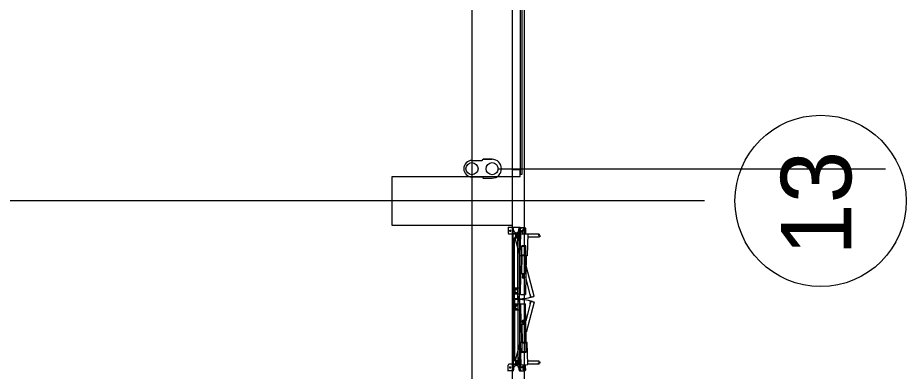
# Model space of a CAD drawing. Extents: x -264031 to -263588, y -1242281 to -1242059.
# Drawn here: x -263801.19 to -263790.15, y -1242163 to -1242158.61 of the extents above; entities that cross this region are included whole.
import ezdxf

# ---------------------------------------------------------------- set-up
doc = ezdxf.new("R2010")
doc.units = 0
doc.layers.add('HESCON_OSI_STAVBY_KFA', color=7, linetype='Continuous')
doc.layers.add('KFA_2D_SITUACIA_DSP', color=7, linetype='Continuous')

msp = doc.modelspace()

# ---------------------------------------------------------------- linework, layer by layer
at = {"layer": 'HESCON_OSI_STAVBY_KFA'}
for p, q in [((-263795.543, -1242083.237), (-263795.543, -1242246.707)), ((-263792.653, -1242160.882), (-263909.343, -1242160.882)), ((-263792.653, -1242160.882), (-263792.653, -1242160.882))]:
    msp.add_line(p, q, dxfattribs=at)
msp.add_circle((-263791.21, -1242160.882), 1.064, dxfattribs=at)
at = {"layer": 'KFA_2D_SITUACIA_DSP'}
for p, q in [((-263795.043, -1242101.769), (-263795.043, -1242226.995)), ((-263794.943, -1242158.452), (-263794.943, -1242160.552)), ((-263794.918, -1242160.552), (-263794.918, -1242158.452)), ((-263795.543, -1242160.379), (-263795.418, -1242160.379)), ((-263795.418, -1242160.379), (-263795.404, -1242160.365)), ((-263795.293, -1242160.365), (-263795.404, -1242160.365)), ((-263795.404, -1242160.365), (-263795.293, -1242160.365)), ((-263795.038, -1242160.582), (-263796.538, -1242160.582)), ((-263796.538, -1242160.582), (-263796.538, -1242161.182)), ((-263795.218, -1242160.485), (-263790.403, -1242160.482)), ((-263794.943, -1242160.497), (-263795.043, -1242160.497)), ((-263795.043, -1242160.497), (-263795.043, -1242160.577)), ((-263795.043, -1242160.577), (-263794.943, -1242160.577)), ((-263795.038, -1242161.182), (-263795.038, -1242160.582)), ((-263794.943, -1242160.537), (-263794.943, -1242160.497)), ((-263794.943, -1242160.577), (-263794.943, -1242160.537)), ((-263794.943, -1242160.552), (-263794.918, -1242160.552)), ((-263795.543, -1242160.585), (-263795.418, -1242160.585)), ((-263795.418, -1242160.585), (-263795.404, -1242160.599)), ((-263795.404, -1242160.599), (-263795.293, -1242160.599)), ((-263796.538, -1242161.182), (-263795.038, -1242161.182)), ((-263795.093, -1242161.208), (-263795.093, -1242161.284)), ((-263795.033, -1242161.214), (-263795.093, -1242161.214)), ((-263795.068, -1242161.241), (-263795.068, -1242161.267)), ((-263795.043, -1242161.208), (-263794.943, -1242161.208)), ((-263795.033, -1242162.102), (-263795.033, -1242161.208)), ((-263795.025, -1242161.224), (-263795.033, -1242161.224)), ((-263795.025, -1242161.245), (-263795.025, -1242161.224)), ((-263794.96, -1242161.245), (-263794.96, -1242161.224)), ((-263794.953, -1242161.224), (-263794.96, -1242161.224)), ((-263794.953, -1242162.102), (-263794.953, -1242161.208)), ((-263794.953, -1242161.213), (-263794.943, -1242161.213)), ((-263794.953, -1242161.213), (-263794.953, -1242161.283)), ((-263794.933, -1242161.223), (-263794.947, -1242161.223)), ((-263794.943, -1242161.213), (-263794.893, -1242161.213)), ((-263794.943, -1242161.213), (-263794.943, -1242161.283)), ((-263794.943, -1242161.232), (-263794.943, -1242161.215)), ((-263794.941, -1242161.215), (-263794.943, -1242161.215)), ((-263794.941, -1242161.232), (-263794.943, -1242161.232)), ((-263794.941, -1242161.232), (-263794.941, -1242161.215)), ((-263794.941, -1242161.23), (-263794.941, -1242161.217)), ((-263794.941, -1242161.217), (-263794.935, -1242161.217)), ((-263794.941, -1242161.223), (-263794.936, -1242161.223)), ((-263794.935, -1242161.23), (-263794.941, -1242161.23)), ((-263794.935, -1242161.217), (-263794.935, -1242161.23)), ((-263794.909, -1242161.289), (-263794.908, -1242161.233)), ((-263794.877, -1242161.233), (-263794.908, -1242161.233)), ((-263794.899, -1242161.223), (-263794.905, -1242161.233)), ((-263794.905, -1242161.233), (-263794.899, -1242161.244)), ((-263794.887, -1242161.223), (-263794.899, -1242161.223)), ((-263794.899, -1242161.244), (-263794.887, -1242161.244)), ((-263794.893, -1242161.218), (-263794.893, -1242161.249)), ((-263794.881, -1242161.233), (-263794.887, -1242161.223)), ((-263794.887, -1242161.244), (-263794.881, -1242161.233)), ((-263794.878, -1242161.234), (-263794.879, -1242161.29)), ((-263795.033, -1242161.294), (-263795.083, -1242161.294)), ((-263795.055, -1242161.254), (-263795.081, -1242161.254)), ((-263794.953, -1242161.288), (-263795.033, -1242161.288)), ((-263794.953, -1242161.294), (-263795.033, -1242161.294)), ((-263795.013, -1242162.097), (-263795.013, -1242161.339)), ((-263794.973, -1242161.339), (-263795.013, -1242161.339)), ((-263795.005, -1242161.288), (-263794.98, -1242161.288)), ((-263795.005, -1242161.288), (-263795.005, -1242161.298)), ((-263795.005, -1242161.298), (-263794.98, -1242161.298)), ((-263795.005, -1242161.339), (-263795.005, -1242161.329)), ((-263795.005, -1242161.329), (-263794.98, -1242161.329)), ((-263795.005, -1242161.343), (-263794.967, -1242161.333)), ((-263795.005, -1242161.339), (-263794.98, -1242161.339)), ((-263794.953, -1242161.54), (-263795.005, -1242161.343)), ((-263794.994, -1242161.298), (-263795.001, -1242161.308)), ((-263795.001, -1242161.319), (-263794.994, -1242161.329)), ((-263794.977, -1242161.325), (-263795.001, -1242161.332)), ((-263794.998, -1242161.341), (-263795.001, -1242161.332)), ((-263794.99, -1242161.329), (-263794.999, -1242161.321)), ((-263794.992, -1242161.298), (-263794.994, -1242161.298)), ((-263794.994, -1242161.329), (-263794.992, -1242161.329)), ((-263794.985, -1242161.308), (-263794.992, -1242161.298)), ((-263794.992, -1242161.329), (-263794.985, -1242161.319)), ((-263794.988, -1242161.328), (-263794.99, -1242161.329)), ((-263794.983, -1242161.317), (-263794.988, -1242161.328)), ((-263794.987, -1242161.305), (-263794.977, -1242161.312)), ((-263794.977, -1242161.314), (-263794.987, -1242161.322)), ((-263794.98, -1242161.288), (-263794.98, -1242161.298)), ((-263794.98, -1242161.339), (-263794.98, -1242161.329)), ((-263794.977, -1242161.301), (-263794.977, -1242161.326)), ((-263794.967, -1242161.301), (-263794.977, -1242161.301)), ((-263794.977, -1242161.312), (-263794.977, -1242161.314)), ((-263794.974, -1242161.335), (-263794.977, -1242161.325)), ((-263794.967, -1242161.326), (-263794.977, -1242161.326)), ((-263794.973, -1242162.097), (-263794.973, -1242161.339)), ((-263794.967, -1242161.333), (-263794.967, -1242161.293)), ((-263794.937, -1242161.293), (-263794.967, -1242161.293)), ((-263794.967, -1242161.301), (-263794.967, -1242161.326)), ((-263794.938, -1242161.333), (-263794.967, -1242161.333)), ((-263794.953, -1242161.386), (-263794.967, -1242161.333)), ((-263794.953, -1242161.283), (-263794.943, -1242161.283)), ((-263794.937, -1242161.294), (-263794.953, -1242161.294)), ((-263794.933, -1242161.272), (-263794.947, -1242161.272)), ((-263794.943, -1242161.253), (-263794.908, -1242161.253)), ((-263794.943, -1242161.281), (-263794.943, -1242161.264)), ((-263794.941, -1242161.264), (-263794.943, -1242161.264)), ((-263794.941, -1242161.281), (-263794.943, -1242161.281)), ((-263794.943, -1242161.564), (-263794.937, -1242161.289)), ((-263794.941, -1242161.281), (-263794.941, -1242161.264)), ((-263794.941, -1242161.279), (-263794.941, -1242161.266)), ((-263794.941, -1242161.266), (-263794.935, -1242161.266)), ((-263794.941, -1242161.272), (-263794.936, -1242161.272)), ((-263794.935, -1242161.279), (-263794.941, -1242161.279)), ((-263794.937, -1242161.289), (-263794.85, -1242161.29)), ((-263794.935, -1242161.266), (-263794.935, -1242161.279)), ((-263794.908, -1242161.254), (-263794.927, -1242161.254)), ((-263794.918, -1242161.253), (-263794.918, -1242161.264)), ((-263794.85, -1242161.29), (-263794.856, -1242161.565)), ((-263794.707, -1242161.333), (-263794.851, -1242161.333)), ((-263794.707, -1242161.293), (-263794.85, -1242161.293)), ((-263794.707, -1242161.305), (-263794.722, -1242161.309)), ((-263794.722, -1242161.309), (-263794.692, -1242161.318)), ((-263794.707, -1242161.293), (-263794.707, -1242161.305)), ((-263794.692, -1242161.318), (-263794.707, -1242161.322)), ((-263794.707, -1242161.322), (-263794.707, -1242161.333)), ((-263794.924, -1242161.564), (-263794.922, -1242161.438)), ((-263794.872, -1242161.439), (-263794.922, -1242161.438)), ((-263794.872, -1242161.449), (-263794.922, -1242161.448)), ((-263794.874, -1242161.565), (-263794.872, -1242161.439)), ((-263794.856, -1242161.565), (-263794.943, -1242161.564)), ((-263794.939, -1242162.045), (-263794.93, -1242161.564)), ((-263794.874, -1242161.555), (-263794.924, -1242161.554)), ((-263794.924, -1242161.787), (-263794.919, -1242161.564)), ((-263794.884, -1242161.788), (-263794.879, -1242161.565)), ((-263794.869, -1242161.565), (-263794.878, -1242162.046)), ((-263794.884, -1242161.788), (-263794.924, -1242161.787)), ((-263794.914, -1242161.792), (-263794.914, -1242161.787)), ((-263794.894, -1242161.792), (-263794.914, -1242161.792)), ((-263794.912, -1242161.792), (-263794.914, -1242161.793)), ((-263794.914, -1242161.799), (-263794.914, -1242161.793)), ((-263794.895, -1242161.792), (-263794.912, -1242161.792)), ((-263794.909, -1242161.799), (-263794.909, -1242161.793)), ((-263794.899, -1242161.8), (-263794.899, -1242161.793)), ((-263794.895, -1242161.792), (-263794.894, -1242161.793)), ((-263794.894, -1242161.792), (-263794.894, -1242161.787)), ((-263794.894, -1242161.8), (-263794.894, -1242161.793)), ((-263794.772, -1242162.066), (-263794.871, -1242161.689)), ((-263794.909, -1242161.808), (-263794.917, -1242161.821)), ((-263794.913, -1242161.8), (-263794.914, -1242161.799)), ((-263794.896, -1242161.8), (-263794.913, -1242161.8)), ((-263794.909, -1242161.808), (-263794.909, -1242161.8)), ((-263794.909, -1242161.808), (-263794.899, -1242161.808)), ((-263794.899, -1242161.808), (-263794.899, -1242161.8)), ((-263794.899, -1242161.808), (-263794.892, -1242161.822)), ((-263794.896, -1242161.8), (-263794.894, -1242161.8)), ((-263794.811, -1242162.076), (-263794.874, -1242161.833)), ((-263795.007, -1242162.04), (-263795.007, -1242161.965)), ((-263794.953, -1242161.965), (-263795.007, -1242161.965)), ((-263795, -1242161.976), (-263794.993, -1242161.972)), ((-263795, -1242161.984), (-263795, -1242161.976)), ((-263794.993, -1242161.988), (-263795, -1242161.984)), ((-263795, -1242162.021), (-263794.993, -1242162.017)), ((-263794.993, -1242161.972), (-263794.986, -1242161.976)), ((-263794.986, -1242161.984), (-263794.993, -1242161.988)), ((-263794.993, -1242162.017), (-263794.986, -1242162.021)), ((-263794.986, -1242161.976), (-263794.986, -1242161.984)), ((-263794.947, -1242161.965), (-263794.953, -1242161.965)), ((-263794.947, -1242162.04), (-263794.947, -1242161.965)), ((-263795.033, -1242162.102), (-263795.033, -1242162.997)), ((-263795.015, -1242162.095), (-263795.015, -1242162.065)), ((-263795.013, -1242162.065), (-263795.015, -1242162.065)), ((-263795.015, -1242162.109), (-263795.015, -1242162.139)), ((-263794.973, -1242162.097), (-263795.013, -1242162.097)), ((-263795.013, -1242162.107), (-263795.013, -1242162.866)), ((-263794.973, -1242162.107), (-263795.013, -1242162.107)), ((-263794.975, -1242162.099), (-263795.011, -1242162.099)), ((-263794.975, -1242162.105), (-263795.011, -1242162.105)), ((-263794.953, -1242162.04), (-263795.007, -1242162.04)), ((-263795, -1242162.029), (-263795, -1242162.021)), ((-263794.993, -1242162.033), (-263795, -1242162.029)), ((-263794.986, -1242162.029), (-263794.993, -1242162.033)), ((-263794.986, -1242162.021), (-263794.986, -1242162.029)), ((-263794.976, -1242162.096), (-263794.967, -1242162.096)), ((-263794.976, -1242162.109), (-263794.967, -1242162.109)), ((-263794.971, -1242162.065), (-263794.973, -1242162.065)), ((-263794.97, -1242162.08), (-263794.973, -1242162.08)), ((-263794.973, -1242162.107), (-263794.973, -1242162.866)), ((-263794.97, -1242162.125), (-263794.973, -1242162.125)), ((-263794.971, -1242162.095), (-263794.971, -1242162.065)), ((-263794.971, -1242162.109), (-263794.971, -1242162.139)), ((-263794.947, -1242162.04), (-263794.953, -1242162.04)), ((-263794.953, -1242162.102), (-263794.953, -1242162.997)), ((-263794.939, -1242162.045), (-263794.878, -1242162.046)), ((-263794.811, -1242162.129), (-263794.874, -1242162.372)), ((-263794.819, -1242162.045), (-263794.821, -1242162.046)), ((-263794.821, -1242162.046), (-263794.814, -1242162.075)), ((-263794.811, -1242162.076), (-263794.772, -1242162.066)), ((-263794.811, -1242162.129), (-263794.772, -1242162.139)), ((-263794.809, -1242162.078), (-263794.774, -1242162.068)), ((-263794.809, -1242162.127), (-263794.774, -1242162.137)), ((-263794.779, -1242162.035), (-263794.781, -1242162.035)), ((-263794.771, -1242162.064), (-263794.779, -1242162.035)), ((-263795.013, -1242162.139), (-263795.015, -1242162.139)), ((-263795.007, -1242162.165), (-263795.007, -1242162.24)), ((-263794.953, -1242162.165), (-263795.007, -1242162.165)), ((-263794.993, -1242162.172), (-263795, -1242162.176)), ((-263795, -1242162.176), (-263795, -1242162.184)), ((-263795, -1242162.184), (-263794.993, -1242162.188)), ((-263794.993, -1242162.217), (-263795, -1242162.221)), ((-263795, -1242162.221), (-263795, -1242162.229)), ((-263795, -1242162.229), (-263794.993, -1242162.233)), ((-263794.986, -1242162.176), (-263794.993, -1242162.172)), ((-263794.993, -1242162.188), (-263794.986, -1242162.184)), ((-263794.986, -1242162.221), (-263794.993, -1242162.217)), ((-263794.993, -1242162.233), (-263794.986, -1242162.229)), ((-263794.986, -1242162.184), (-263794.986, -1242162.176)), ((-263794.986, -1242162.229), (-263794.986, -1242162.221)), ((-263794.971, -1242162.139), (-263794.973, -1242162.139)), ((-263794.947, -1242162.165), (-263794.953, -1242162.165)), ((-263794.947, -1242162.165), (-263794.947, -1242162.24)), ((-263794.939, -1242162.16), (-263794.878, -1242162.159)), ((-263794.939, -1242162.16), (-263794.93, -1242162.641)), ((-263794.869, -1242162.64), (-263794.878, -1242162.159)), ((-263794.772, -1242162.139), (-263794.871, -1242162.516)), ((-263794.821, -1242162.159), (-263794.814, -1242162.13)), ((-263794.819, -1242162.16), (-263794.821, -1242162.159)), ((-263794.779, -1242162.17), (-263794.781, -1242162.17)), ((-263794.771, -1242162.141), (-263794.779, -1242162.17)), ((-263794.953, -1242162.24), (-263795.007, -1242162.24)), ((-263794.947, -1242162.24), (-263794.953, -1242162.24)), ((-263794.884, -1242162.417), (-263794.924, -1242162.418)), ((-263794.924, -1242162.418), (-263794.919, -1242162.641)), ((-263794.909, -1242162.397), (-263794.917, -1242162.384)), ((-263794.913, -1242162.405), (-263794.914, -1242162.406)), ((-263794.914, -1242162.406), (-263794.914, -1242162.412)), ((-263794.912, -1242162.413), (-263794.914, -1242162.412)), ((-263794.914, -1242162.413), (-263794.914, -1242162.418)), ((-263794.894, -1242162.413), (-263794.914, -1242162.413)), ((-263794.896, -1242162.405), (-263794.913, -1242162.405)), ((-263794.895, -1242162.413), (-263794.912, -1242162.413)), ((-263794.909, -1242162.397), (-263794.899, -1242162.397)), ((-263794.909, -1242162.397), (-263794.909, -1242162.405)), ((-263794.909, -1242162.406), (-263794.909, -1242162.412)), ((-263794.899, -1242162.397), (-263794.892, -1242162.383)), ((-263794.899, -1242162.397), (-263794.899, -1242162.405)), ((-263794.899, -1242162.405), (-263794.899, -1242162.412)), ((-263794.896, -1242162.405), (-263794.894, -1242162.405)), ((-263794.895, -1242162.413), (-263794.894, -1242162.412)), ((-263794.894, -1242162.405), (-263794.894, -1242162.412)), ((-263794.894, -1242162.413), (-263794.894, -1242162.418)), ((-263794.884, -1242162.417), (-263794.879, -1242162.64)), ((-263794.953, -1242162.665), (-263795.005, -1242162.862)), ((-263794.856, -1242162.64), (-263794.943, -1242162.641)), ((-263794.943, -1242162.641), (-263794.937, -1242162.916)), ((-263794.924, -1242162.641), (-263794.922, -1242162.767)), ((-263794.874, -1242162.65), (-263794.924, -1242162.651)), ((-263794.874, -1242162.64), (-263794.872, -1242162.766)), ((-263794.85, -1242162.915), (-263794.856, -1242162.64)), ((-263794.872, -1242162.756), (-263794.922, -1242162.757)), ((-263794.872, -1242162.766), (-263794.922, -1242162.767)), ((-263794.973, -1242162.866), (-263795.013, -1242162.866)), ((-263795.005, -1242162.862), (-263794.967, -1242162.872)), ((-263795.005, -1242162.866), (-263795.005, -1242162.876)), ((-263795.005, -1242162.866), (-263794.98, -1242162.866)), ((-263795.005, -1242162.876), (-263794.98, -1242162.876)), ((-263794.998, -1242162.864), (-263795.001, -1242162.873)), ((-263794.977, -1242162.88), (-263795.001, -1242162.873)), ((-263795.001, -1242162.886), (-263794.994, -1242162.876)), ((-263794.994, -1242162.907), (-263795.001, -1242162.897)), ((-263794.99, -1242162.876), (-263794.999, -1242162.884)), ((-263794.994, -1242162.876), (-263794.992, -1242162.876)), ((-263794.992, -1242162.876), (-263794.985, -1242162.886)), ((-263794.985, -1242162.897), (-263794.992, -1242162.907)), ((-263794.988, -1242162.877), (-263794.99, -1242162.876)), ((-263794.983, -1242162.888), (-263794.988, -1242162.877)), ((-263794.977, -1242162.89), (-263794.987, -1242162.883)), ((-263794.987, -1242162.9), (-263794.977, -1242162.892)), ((-263794.98, -1242162.866), (-263794.98, -1242162.876)), ((-263794.974, -1242162.87), (-263794.977, -1242162.88)), ((-263794.977, -1242162.904), (-263794.977, -1242162.879)), ((-263794.967, -1242162.879), (-263794.977, -1242162.879)), ((-263794.977, -1242162.892), (-263794.977, -1242162.89)), ((-263794.953, -1242162.819), (-263794.967, -1242162.872)), ((-263794.967, -1242162.871), (-263794.967, -1242162.911)), ((-263794.938, -1242162.871), (-263794.967, -1242162.871)), ((-263794.967, -1242162.904), (-263794.967, -1242162.879)), ((-263794.707, -1242162.871), (-263794.851, -1242162.871)), ((-263794.722, -1242162.896), (-263794.692, -1242162.887)), ((-263794.707, -1242162.9), (-263794.722, -1242162.896)), ((-263794.707, -1242162.883), (-263794.707, -1242162.871)), ((-263794.692, -1242162.887), (-263794.707, -1242162.883)), ((-263794.707, -1242162.911), (-263794.707, -1242162.9)), ((-263795.093, -1242162.997), (-263795.093, -1242162.921)), ((-263795.033, -1242162.991), (-263795.093, -1242162.991)), ((-263795.033, -1242162.911), (-263795.083, -1242162.911)), ((-263795.055, -1242162.951), (-263795.081, -1242162.951)), ((-263795.068, -1242162.964), (-263795.068, -1242162.938)), ((-263794.953, -1242162.911), (-263795.033, -1242162.911)), ((-263794.953, -1242162.917), (-263795.033, -1242162.917)), ((-263795.025, -1242162.981), (-263795.033, -1242162.981)), ((-263795.025, -1242162.96), (-263795.025, -1242162.981)), ((-263795.005, -1242162.907), (-263794.98, -1242162.907)), ((-263795.005, -1242162.917), (-263795.005, -1242162.907)), ((-263795.005, -1242162.917), (-263794.98, -1242162.917)), ((-263794.992, -1242162.907), (-263794.994, -1242162.907)), ((-263794.98, -1242162.917), (-263794.98, -1242162.907)), ((-263794.967, -1242162.904), (-263794.977, -1242162.904)), ((-263794.937, -1242162.911), (-263794.967, -1242162.911)), ((-263794.96, -1242162.96), (-263794.96, -1242162.981)), ((-263794.953, -1242162.981), (-263794.96, -1242162.981)), ((-263794.937, -1242162.911), (-263794.953, -1242162.911)), ((-263794.953, -1242162.922), (-263794.943, -1242162.922)), ((-263794.953, -1242162.992), (-263794.953, -1242162.922)), ((-263794.953, -1242162.992), (-263794.943, -1242162.992)), ((-263794.933, -1242162.932), (-263794.947, -1242162.932)), ((-263794.933, -1242162.981), (-263794.947, -1242162.981)), ((-263794.943, -1242162.992), (-263794.943, -1242162.922)), ((-263794.943, -1242162.924), (-263794.943, -1242162.941)), ((-263794.941, -1242162.924), (-263794.943, -1242162.924)), ((-263794.941, -1242162.941), (-263794.943, -1242162.941)), ((-263794.943, -1242162.951), (-263794.908, -1242162.951)), ((-263794.943, -1242162.973), (-263794.943, -1242162.99)), ((-263794.941, -1242162.973), (-263794.943, -1242162.973)), ((-263794.941, -1242162.99), (-263794.943, -1242162.99)), ((-263794.943, -1242162.991), (-263794.893, -1242162.991)), ((-263794.941, -1242162.924), (-263794.941, -1242162.941)), ((-263794.941, -1242162.926), (-263794.941, -1242162.939)), ((-263794.935, -1242162.926), (-263794.941, -1242162.926)), ((-263794.941, -1242162.932), (-263794.936, -1242162.932)), ((-263794.941, -1242162.939), (-263794.935, -1242162.939)), ((-263794.941, -1242162.973), (-263794.941, -1242162.99)), ((-263794.941, -1242162.975), (-263794.941, -1242162.988)), ((-263794.935, -1242162.975), (-263794.941, -1242162.975)), ((-263794.941, -1242162.981), (-263794.936, -1242162.981)), ((-263794.941, -1242162.988), (-263794.935, -1242162.988)), ((-263794.937, -1242162.916), (-263794.85, -1242162.915)), ((-263794.935, -1242162.939), (-263794.935, -1242162.926)), ((-263794.935, -1242162.988), (-263794.935, -1242162.975)), ((-263794.908, -1242162.951), (-263794.927, -1242162.951)), ((-263794.918, -1242162.951), (-263794.918, -1242162.941)), ((-263794.909, -1242162.916), (-263794.908, -1242162.972)), ((-263794.877, -1242162.971), (-263794.908, -1242162.971)), ((-263794.905, -1242162.971), (-263794.899, -1242162.961)), ((-263794.899, -1242162.982), (-263794.905, -1242162.971)), ((-263794.899, -1242162.961), (-263794.887, -1242162.961)), ((-263794.887, -1242162.982), (-263794.899, -1242162.982)), ((-263794.893, -1242162.987), (-263794.893, -1242162.956)), ((-263794.887, -1242162.961), (-263794.881, -1242162.971)), ((-263794.881, -1242162.971), (-263794.887, -1242162.982)), ((-263794.878, -1242162.971), (-263794.879, -1242162.915)), ((-263794.707, -1242162.911), (-263794.85, -1242162.911))]:
    msp.add_line(p, q, dxfattribs=at)
msp.add_lwpolyline([(-263794.893, -1242227.382), (-263808.968, -1242241.457), (-263894.968, -1242241.457), (-263909.043, -1242227.382), (-263909.043, -1242196.333), (-263914.143, -1242196.333), (-263914.143, -1242132.433), (-263909.043, -1242132.433), (-263909.043, -1242101.382), (-263894.968, -1242087.307), (-263808.968, -1242087.307), (-263794.893, -1242101.382), (-263794.893, -1242227.382)], dxfattribs=at)
for centre, radius in [((-263795.543, -1242160.482), 0.075), ((-263795.293, -1242160.482), 0.075), ((-263794.893, -1242161.233), 0.0126), ((-263794.893, -1242161.233), 0.0102), ((-263795.068, -1242161.254), 0.008), ((-263794.905, -1242161.828), 0.00952), ((-263794.905, -1242161.828), 0.00645), ((-263794.905, -1242161.828), 0.005), ((-263794.993, -1242161.98), 0.0084), ((-263794.993, -1242162.025), 0.0084), ((-263794.993, -1242161.98), 0.0068), ((-263794.993, -1242162.025), 0.0068), ((-263794.993, -1242162.18), 0.0084), ((-263794.993, -1242162.225), 0.0084), ((-263794.993, -1242162.18), 0.0068), ((-263794.993, -1242162.225), 0.0068), ((-263794.905, -1242162.377), 0.00952), ((-263794.905, -1242162.377), 0.00645), ((-263794.905, -1242162.377), 0.005), ((-263795.068, -1242162.951), 0.008), ((-263794.893, -1242162.971), 0.0126), ((-263794.893, -1242162.971), 0.0102)]:
    msp.add_circle(centre, radius, dxfattribs=at)
for centre, radius, start, end in [((-263795.543, -1242160.482), 0.103, 90, 270), ((-263795.293, -1242160.482), 0.117, 270, 90), ((-263794.993, -1242161.245), 0.0325, 180, 0), ((-263794.942, -1242161.22), 0.0068, 330, 30), ((-263794.942, -1242161.227), 0.0068, 330, 30), ((-263794.893, -1242161.233), 0.015, 358.86, 178.86), ((-263794.893, -1242161.233), 0.02, 317.4504, 90), ((-263795.083, -1242161.284), 0.01, 180, 270), ((-263794.993, -1242161.313), 0.01, 323.6139, 216.3861), ((-263794.993, -1242161.313), 0.01, 53.6139, 306.3861), ((-263794.993, -1242161.313), 0.01, 338.6139, 231.3861), ((-263794.993, -1242161.313), 0.01, 143.6139, 36.3861), ((-263794.942, -1242161.269), 0.0068, 330, 30), ((-263794.942, -1242161.276), 0.0068, 330, 30), ((-263794.918, -1242161.254), 0.008, 176.4167, 3.5833), ((-263794.911, -1242161.796), 0.00432, 54.2666, 123.4534), ((-263794.904, -1242161.808), 0.0161, 71.1601, 106.5599), ((-263794.897, -1242161.797), 0.00432, 54.2666, 123.4534), ((-263794.899, -1242161.793), 0.0001, 178.86, 248.0468), ((-263794.905, -1242161.828), 0.014, 150.1229, 27.5971), ((-263794.911, -1242161.796), 0.00432, 234.2666, 303.4534), ((-263794.904, -1242161.784), 0.0161, 251.1601, 286.5599), ((-263794.899, -1242161.8), 0.0001, 109.6732, 178.86), ((-263794.897, -1242161.796), 0.00432, 234.2666, 303.4534), ((-263795.011, -1242162.095), 0.004, 180, 270), ((-263795.011, -1242162.109), 0.004, 90, 180), ((-263794.993, -1242161.313), 0.786, 270, 285), ((-263794.993, -1242162.891), 0.786, 75, 90), ((-263794.975, -1242162.095), 0.004, 270, 0), ((-263794.975, -1242162.109), 0.004, 0, 90), ((-263794.81, -1242162.074), 0.004, 195, 285), ((-263794.81, -1242162.131), 0.004, 75, 165), ((-263794.775, -1242162.065), 0.004, 285, 15), ((-263794.775, -1242162.14), 0.004, 345, 75), ((-263794.905, -1242162.377), 0.014, 332.4029, 209.8771), ((-263794.911, -1242162.409), 0.00432, 56.5466, 125.7334), ((-263794.911, -1242162.409), 0.00432, 236.5466, 305.7334), ((-263794.904, -1242162.421), 0.0161, 73.4401, 108.8399), ((-263794.904, -1242162.397), 0.0161, 253.4401, 288.8399), ((-263794.897, -1242162.409), 0.00432, 56.5466, 125.7334), ((-263794.899, -1242162.405), 0.0001, 181.14, 250.3268), ((-263794.897, -1242162.408), 0.00432, 236.5466, 305.7334), ((-263794.899, -1242162.412), 0.0001, 111.9532, 181.14), ((-263794.993, -1242162.891), 0.01, 323.6139, 216.3861), ((-263794.993, -1242162.891), 0.01, 53.6139, 306.3861), ((-263794.993, -1242162.891), 0.01, 128.6139, 21.3861), ((-263794.993, -1242162.891), 0.01, 143.6139, 36.3861), ((-263795.083, -1242162.921), 0.01, 90, 180), ((-263794.993, -1242162.96), 0.0325, 0, 180), ((-263794.942, -1242162.929), 0.0068, 330, 30), ((-263794.942, -1242162.936), 0.0068, 330, 30), ((-263794.942, -1242162.978), 0.0068, 330, 30), ((-263794.942, -1242162.985), 0.0068, 330, 30), ((-263794.918, -1242162.951), 0.008, 356.4167, 183.5833), ((-263794.893, -1242162.971), 0.015, 181.14, 1.14), ((-263794.893, -1242162.971), 0.02, 270, 42.5496)]:
    msp.add_arc(centre, radius, start, end, dxfattribs=at)

# ---------------------------------------------------------------- texts
at = {"layer": 'HESCON_OSI_STAVBY_KFA'}
msp.add_text('13', height=0.875, rotation=90, dxfattribs=at).set_placement((-263790.829, -1242161.562))

doc.saveas('drawing.dxf')
